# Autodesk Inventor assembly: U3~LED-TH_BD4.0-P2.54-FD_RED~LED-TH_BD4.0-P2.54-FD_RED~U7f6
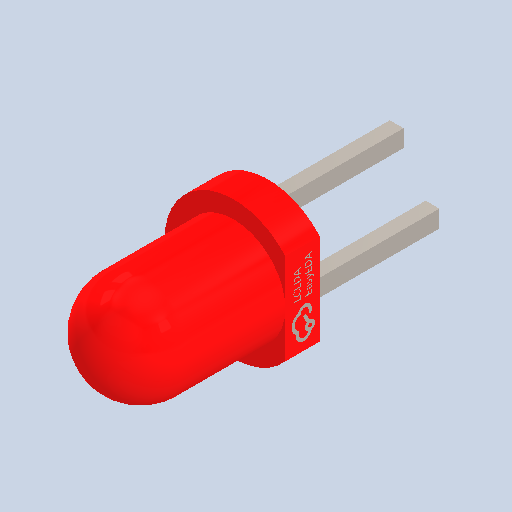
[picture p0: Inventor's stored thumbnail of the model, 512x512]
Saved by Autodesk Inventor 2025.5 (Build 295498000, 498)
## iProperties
Created: 2026-10
Part Number: U3~LED-TH_BD4.0-P2.54-FD_RED~LED-TH_BD4.0-P2.54-FD_RED~U7f6
Document SubType Name: Assembly
Designer: Luis M
Author: Luis M
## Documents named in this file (2)
- C:\Users\Luis M\Downloads\3D_PCB1_2026-10-28\U3~LED-TH_BD4.0-P2.54-FD_RED~LED-TH_BD4.0-P2.54-FD_RED~U7f6.iam
- C:\Users\Luis M\Downloads\3D_PCB1_2026-10-28\LED-TH_BD4.0-P2.54-FD_RED~LED-TH_BD4.0-P2.54-FD_RED~MGTW.ipt
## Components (1 placed, 1 different names)
1. U3->0
